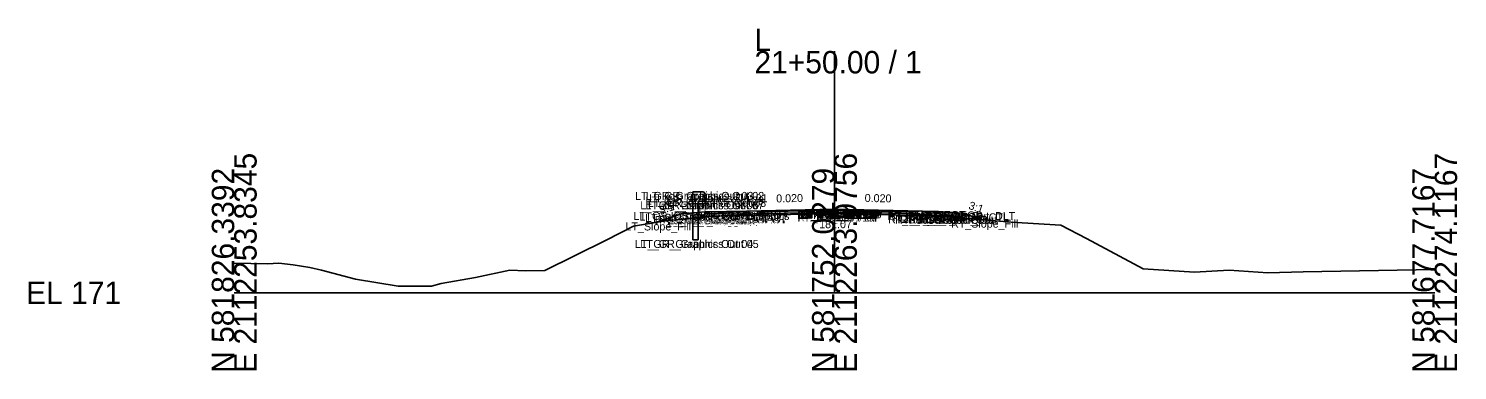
# Model space of a CAD drawing. Extents: x -486 to 1153, y -333 to 9539.
# Drawn here: x 974.3 to 1152.8, y 2490.3 to 2533 of the extents above; entities that cross this region are included whole.
import ezdxf

# ---------------------------------------------------------------- set-up
doc = ezdxf.new("R2010")
doc.units = 0
for name, color, linetype in [('Default', 7, 'Continuous'), ('Exist Cross Section Cell', 7, 'Continuous'), ('Exist XS Ground Line', 7, 'Continuous'), ('Prop CMT Guardrail Graphics', 7, 'Continuous'), ('Prop CMT Pvmt Course 1', 7, 'Continuous'), ('Prop CMT Pvmt Course 2', 7, 'Continuous'), ('Prop CMT Pvmt Course 3', 7, 'Continuous'), ('Prop CMT Pvmt Surface', 7, 'Continuous'), ('Prop CMT Pvmt Surface Shoulder', 7, 'Continuous'), ('Prop CMT Shld Paved Course 1', 7, 'Continuous'), ('Prop CMT Shld Paved Course 2', 7, 'Continuous'), ('Prop CMT Shld Paved Course 3', 7, 'Continuous'), ('Prop CMT Slope Grass', 7, 'Continuous'), ('Prop CMT Subgrade Earthwork', 7, 'Continuous'), ('Prop XS Earthwork Shape', 7, 'Continuous'), ('Prop XS SE Text', 7, 'Continuous'), ('Prop XS Side Slope Text', 7, 'Continuous'), ('Scratch_Level_0', 7, 'Continuous'), ('Scratch_Level_1', 7, 'Continuous')]:
    doc.layers.add(name, color=color, linetype=linetype)

msp = doc.modelspace()

# ---------------------------------------------------------------- linework, layer by layer
at = {"layer": 'Exist Cross Section Cell'}
for p, q in [((1075, 2500), (1075, 2530.2)), ((1000, 2500), (1075, 2500)), ((1075, 2500), (1150, 2500))]:
    msp.add_line(p, q, dxfattribs=at)
at = {"layer": 'Exist XS Ground Line'}
for p, q in [((1049.88, 2508.31), (1053.87, 2509)), ((1053.87, 2509), (1058.7, 2509.43)), ((1058.7, 2509.43), (1065.4, 2509.89)), ((1065.4, 2509.89), (1071.99, 2510)), ((1071.99, 2510), (1074.9, 2510.07)), ((1074.9, 2510.07), (1081.81, 2509.96)), ((1081.81, 2509.96), (1084.78, 2509.91)), ((1084.78, 2509.91), (1090.24, 2509.4)), ((1090.24, 2509.4), (1097.09, 2508.83)), ((1097.09, 2508.83), (1103.28, 2508.45)), ((1103.28, 2508.45), (1106.48, 2506.79)), ((1046.47, 2506.56), (1049.88, 2508.31)), ((1106.48, 2506.79), (1113.59, 2502.98)), ((1038.83, 2502.77), (1046.47, 2506.56)), ((1000, 2503.69), (1004.16, 2503.62)), ((1004.16, 2503.62), (1005.57, 2503.71)), ((1005.57, 2503.71), (1007.38, 2503.5)), ((1007.38, 2503.5), (1009.45, 2503.14)), ((1009.45, 2503.14), (1010.92, 2502.82)), ((1010.92, 2502.82), (1015.17, 2501.71)), ((1015.17, 2501.71), (1020.49, 2500.83)), ((1025.86, 2501.15), (1030.15, 2501.91)), ((1030.15, 2501.91), (1034.42, 2502.82)), ((1034.42, 2502.82), (1036.39, 2502.73)), ((1036.39, 2502.73), (1038.83, 2502.77)), ((1113.59, 2502.98), (1120, 2502.56)), ((1120, 2502.56), (1124.3, 2502.82)), ((1124.3, 2502.82), (1129.16, 2502.51)), ((1129.16, 2502.51), (1133.56, 2502.6)), ((1133.56, 2502.6), (1150, 2502.93)), ((1020.49, 2500.83), (1024.67, 2500.82)), ((1024.67, 2500.82), (1025.86, 2501.15))]:
    msp.add_line(p, q, dxfattribs=at)
at = {"layer": 'Prop CMT Guardrail Graphics'}
for points in [[(1057.3, 2506.6), (1057.3, 2512.6)], [(1057.3, 2512.6), (1058.63, 2512.6), (1058.9, 2512.31)], [(1058.9, 2512.31), (1058.63, 2512.02)], [(1058.63, 2512.02), (1058.9, 2511.73)], [(1058.9, 2511.73), (1058.63, 2511.43), (1057.96, 2511.43)], [(1057.96, 2511.43), (1057.96, 2506.6)], [(1057.96, 2506.6), (1057.3, 2506.6)]]:
    msp.add_lwpolyline(points, dxfattribs=at)
at = {"layer": 'Prop CMT Pvmt Course 1'}
for points in [[(1075, 2510.43), (1064, 2510.21)], [(1064, 2510.21), (1064, 2510)], [(1075, 2510.43), (1086, 2510.21)], [(1086, 2510.21), (1086, 2510)]]:
    msp.add_lwpolyline(points, dxfattribs=at)
at = {"layer": 'Prop CMT Pvmt Course 2'}
for points in [[(1065.4, 2510.22), (1065.4, 2509.7)], [(1064, 2509.67), (1065.4, 2509.7)], [(1084.78, 2510.13), (1084.78, 2509.69)], [(1086, 2510), (1086, 2509.67)]]:
    msp.add_lwpolyline(points, dxfattribs=at)
at = {"layer": 'Prop CMT Pvmt Course 3'}
for points in [[(1065.4, 2509.7), (1064, 2509.67)], [(1064, 2509.67), (1064, 2509.67)], [(1075, 2509.89), (1075, 2509.89)], [(1075, 2509.89), (1075, 2509.89)], [(1084.78, 2509.69), (1086, 2509.67)], [(1086, 2509.67), (1086, 2509.67)]]:
    msp.add_lwpolyline(points, dxfattribs=at)
at = {"layer": 'Prop CMT Pvmt Surface'}
for points in [[(1075, 2510.43), (1064, 2510.21)], [(1075, 2510.32), (1065.4, 2510.13)], [(1075, 2510.43), (1086, 2510.21)], [(1075, 2510.32), (1084.78, 2510.13)]]:
    msp.add_lwpolyline(points, dxfattribs=at)
at = {"layer": 'Prop CMT Pvmt Surface Shoulder'}
for points in [[(1064, 2510.21), (1059, 2510.11)], [(1086, 2510.21), (1088, 2510.17)]]:
    msp.add_lwpolyline(points, dxfattribs=at)
at = {"layer": 'Prop CMT Shld Paved Course 1'}
for points in [[(1064, 2510.21), (1059, 2510.11), (1058.79, 2509.9)], [(1064, 2510), (1064, 2510.21)], [(1086, 2510.21), (1088, 2510.17), (1088.21, 2509.96)], [(1086, 2510), (1086, 2510.21)], [(1058.79, 2509.9), (1064, 2510)], [(1088.21, 2509.96), (1086, 2510)]]:
    msp.add_lwpolyline(points, dxfattribs=at)
at = {"layer": 'Prop CMT Shld Paved Course 2'}
for points in [[(1064, 2510), (1058.79, 2509.9), (1058.45, 2509.56)], [(1058.45, 2509.56), (1064, 2509.67)], [(1064, 2509.67), (1064, 2510)], [(1086, 2510), (1088.21, 2509.96), (1088.55, 2509.62)], [(1086, 2509.67), (1086, 2510)], [(1088.55, 2509.62), (1086, 2509.67)]]:
    msp.add_lwpolyline(points, dxfattribs=at)
at = {"layer": 'Prop CMT Shld Paved Course 3'}
for points in [[(1064, 2509.67), (1058.45, 2509.56)], [(1058.45, 2509.56), (1058.45, 2509.56), (1058.45, 2509.56)], [(1064, 2509.67), (1064, 2509.67)], [(1086, 2509.67), (1088.55, 2509.62)], [(1086, 2509.67), (1086, 2509.67)], [(1088.55, 2509.62), (1088.55, 2509.62), (1088.55, 2509.62)]]:
    msp.add_lwpolyline(points, dxfattribs=at)
at = {"layer": 'Prop CMT Slope Grass'}
for points in [[(1088, 2510.17), (1091, 2509.93), (1093.39, 2509.14)], [(1055.9, 2509.86), (1052.65, 2508.79)], [(1058.9, 2510.1), (1055.9, 2509.86)], [(1059, 2510.11), (1058.9, 2510.1)]]:
    msp.add_lwpolyline(points, dxfattribs=at)
at = {"layer": 'Prop CMT Subgrade Earthwork'}
for points in [[(1058.45, 2509.56), (1057.98, 2510.03)], [(1064, 2509.67), (1058.45, 2509.56)], [(1065.4, 2509.7), (1064, 2509.67)], [(1084.78, 2509.69), (1086, 2509.67)], [(1086, 2509.67), (1088.55, 2509.62)], [(1088.55, 2509.62), (1089.02, 2510.09)]]:
    msp.add_lwpolyline(points, dxfattribs=at)
at = {"layer": 'Prop XS Earthwork Shape'}
for points in [[(1052.65, 2508.79), (1053.87, 2509), (1058.7, 2509.43), (1061.34, 2509.61), (1058.45, 2509.56), (1057.98, 2510.03), (1055.9, 2509.86)], [(1075, 2509.89), (1064, 2509.67), (1061.34, 2509.61), (1065.4, 2509.89), (1071.99, 2510), (1074.9, 2510.07), (1081.81, 2509.96), (1084.78, 2509.91), (1087.77, 2509.63), (1086, 2509.67)], [(1087.77, 2509.63), (1088.55, 2509.62), (1089.02, 2510.09), (1091, 2509.93), (1093.39, 2509.14), (1090.24, 2509.4)]]:
    msp.add_lwpolyline(points, close=True, dxfattribs=at)
at = {"layer": 'Scratch_Level_1'}
for p, q in [((1075, 2510.32), (1075, 2510.32)), ((1065.4, 2509.89), (1071.99, 2510)), ((1071.99, 2510), (1074.9, 2510.07)), ((1074.9, 2510.07), (1081.81, 2509.96)), ((1081.81, 2509.96), (1084.78, 2509.91))]:
    msp.add_line(p, q, dxfattribs=at)
for points in [[(1075, 2510.32), (1065.4, 2510.13)], [(1084.78, 2510.13), (1075, 2510.32)], [(1065.4, 2510.13), (1065.4, 2509.89)], [(1084.78, 2509.91), (1084.78, 2510.13)]]:
    msp.add_lwpolyline(points, dxfattribs=at)

# ---------------------------------------------------------------- texts
at = {"layer": 'Default'}
for s, height, p in [('181.07', 1, (1073.09, 2508.07)), ('-', 0.0001, (1000, 2500))]:
    msp.add_text(s, height=height, dxfattribs=at).set_placement(p)
at = {"layer": 'Exist Cross Section Cell'}
for s, p in [('L', (1065, 2530.2)), ('21+50.00 / 1', (1065, 2527.4)), ('EL 171', (974, 2498.6))]:
    msp.add_text(s, height=2.8, dxfattribs=at).set_placement(p)
for s, p in [('E 2112253.8345', (1002.8, 2490)), ('E 2112263.9756', (1077.8, 2490)), ('E 2112274.1167', (1152.8, 2490)), ('N 581826.3392', (1000, 2490)), ('N 581752.0279', (1075, 2490)), ('N 581677.7167', (1150, 2490))]:
    msp.add_text(s, height=2.8, rotation=90, dxfattribs=at).set_placement(p)
at = {"layer": 'Prop XS SE Text'}
for rotation, p in [(1.1458, (1067.73, 2511.28)), (358.8542, (1078.77, 2511.35))]:
    msp.add_text('0.020', height=1, rotation=rotation, dxfattribs=at).set_placement(p)
at = {"layer": 'Prop XS Side Slope Text'}
for rotation, p in [(18.2629, (1053.29, 2509.79)), (341.7371, (1091.68, 2510.5))]:
    msp.add_text('3:1', height=1, rotation=rotation, dxfattribs=at).set_placement(p)
at = {"layer": 'Scratch_Level_0'}
for s, p in [('LT_GR_Graphics Out 03', (1050.08, 2511.6)), ('LT_GR_Graphics Out 09', (1051.4, 2511.02)), ('LT_GR_Graphics Out 02', (1051.43, 2511.6)), ('LT_GR_Graphics Out 01', (1051.85, 2511.31)), ('LT_GR_Graphics Out 06', (1050.74, 2510.43)), ('LT_GR_Graphics Out 07', (1051.39, 2510.43)), ('LT_GR_Graphics Out 08', (1051.67, 2510.73)), ('LT_PV1_OEOT', (1059.87, 2509.21)), ('RT_PV2_OEEOP', (1070.33, 2509.22)), ('LT_PV2_OEEOP', (1070.39, 2509.22)), ('RT_PV1_OEEOP', (1070.45, 2509.3)), ('LT_PV1_OEEOP', (1070.51, 2509.3)), ('RT_PV2_IEEOP', (1070.71, 2509.22)), ('LT_PV2_IEEOP', (1070.77, 2509.22)), ('RT_PV1_IEEOP', (1070.83, 2509.3)), ('LT_PV1_IEEOP', (1070.89, 2509.3)), ('PV2_PGL', (1072.35, 2509.22)), ('PV1_PGL', (1072.47, 2509.43)), ('RT_PV1_OEOT', (1081.81, 2509.21)), ('RT_PS1_OEOP', (1083.85, 2509.17)), ('LT_Slope_Fill', (1048.89, 2507.79)), ('LT_GS_OS_GR_Face_Graphics', (1049.9, 2509.1)), ('LT_Sub_Trench_Out_DLT', (1050.63, 2509.03)), ('LT_GS_OS_CTL', (1051.36, 2508.86)), ('LT_Sub_Trench_Out', (1052.56, 2508.56)), ('LT_PS3_Shelf_Out', (1053.1, 2508.56)), ('LT_PS3_OEOP', (1054.23, 2508.56)), ('LT_PS2_OEOP', (1054.57, 2508.9)), ('LT_PS1_OEOP', (1054.91, 2509.11)), ('LT_PV2_OEOT', (1059.75, 2509)), ('LT_PV3_OEOT', (1059.75, 2508.67)), ('LT_Sub_OEOT', (1059.77, 2508.67)), ('RT_PV3_OEEOP', (1070.33, 2508.89)), ('RT_Sub_OEEOP', (1070.36, 2508.89)), ('LT_PV3_OEEOP', (1070.39, 2508.89)), ('LT_Sub_OEEOP', (1070.42, 2508.89)), ('RT_Sub_Trench_Out_DLT', (1081.61, 2509.09)), ('RT_PV2_OEOT', (1081.69, 2509)), ('RT_PV3_OEOT', (1081.69, 2508.67)), ('RT_Sub_OEOT', (1081.71, 2508.67)), ('RT_Sub_Trench_Out', (1082.6, 2508.62)), ('RT_PS3_Shelf_Out', (1083.15, 2508.62)), ('RT_PS2_OEOP', (1083.94, 2508.96)), ('RT_PS3_OEOP', (1084.28, 2508.62)), ('RT_GS_OS_CTL', (1086.4, 2508.93)), ('RT_Slope_Fill', (1089.57, 2508.14)), ('LT_GR_Graphics Out 04', (1050.07, 2505.6)), ('LT_GR_Graphics Out 05', (1050.74, 2505.6))]:
    msp.add_text(s, height=1, dxfattribs=at).set_placement(p)

doc.saveas('drawing.dxf')
